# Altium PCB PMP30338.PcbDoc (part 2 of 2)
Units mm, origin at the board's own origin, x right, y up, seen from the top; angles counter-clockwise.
Board outline 50.04 x 70.1 mm, 4 copper layers (Top Layer, GND, Signal Layer, Bottom Layer), stack 2.028 mm thick; 61 components, 55 nets, 302 pads, 122 vias.
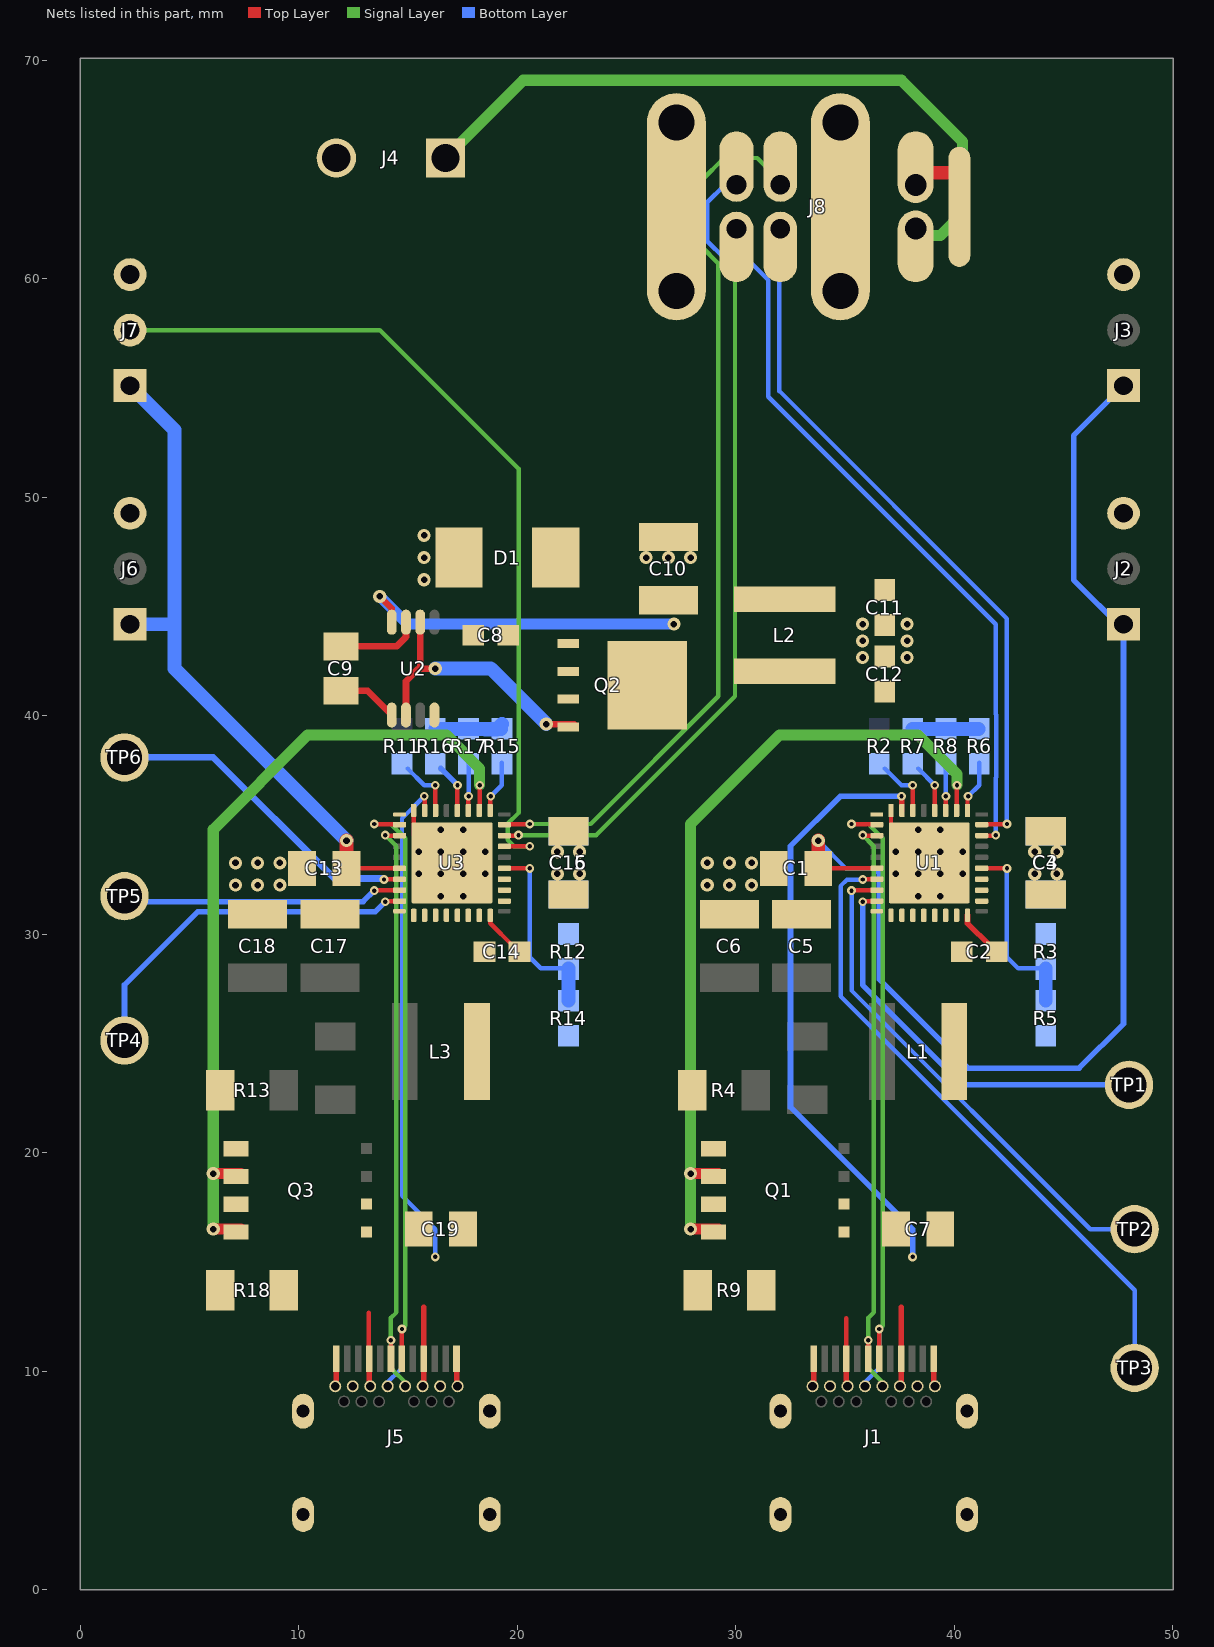
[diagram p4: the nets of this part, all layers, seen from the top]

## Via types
v1: diameter 0.6, hole 0.3, Top Layer to Bottom Layer, 66 vias
v2: diameter 0.4, hole 0.2, Top Layer to Bottom Layer, 52 vias
v3: diameter 5, hole 3, Top Layer to Bottom Layer, 4 vias

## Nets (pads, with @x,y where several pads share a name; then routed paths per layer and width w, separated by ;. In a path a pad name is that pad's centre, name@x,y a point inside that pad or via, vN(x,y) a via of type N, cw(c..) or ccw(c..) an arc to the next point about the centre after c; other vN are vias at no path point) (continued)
CTRL2_2: J7.2 U3.6 | length 39.9
  Top Layer w0.203: U3.6@19.418,34.024 19.418,34.03 v2@20.568,34.03
  Signal Layer w0.203: J7.2@2.286,57.658 13.716,57.658 20.066,51.308 20.066,35.56 19.564,35.058 19.564,34.336 19.858,34.042 20.568,34.042 v2(20.574,34.036)
DN_IN_1: J1.A7 J1.B7 U1.17 | length 29.6
  Top Layer w0.203: v2@35.312,35.046 36.462,35.046 U1.17@36.462,35.024 ; J1.A7@36.572,10.58 v2@36.572,11.934
  Signal Layer w0.203: v2(35.306,35.052) 36.068,35.052 36.725,34.395 36.725,12.087 v2(36.576,11.938)
  Bottom Layer w0.203: J1.B7@35.814,9.398 36.576,10.16 v2(36.576,11.938)
DN_IN_2: J5.A7 J5.B7 U3.17 | length 29.6
  Top Layer w0.203: v2@13.468,35.046 14.618,35.046 U3.17@14.618,35.024 ; J5.A7@14.728,10.58 v2@14.728,11.934
  Signal Layer w0.203: v2(13.462,35.052) 14.224,35.052 14.881,34.395 14.881,31.855 ; v2(14.732,11.938) 14.881,12.087 14.881,31.842
  Bottom Layer w0.203: J5.B7@13.97,9.398 14.732,10.16 v2(14.732,11.938)
DN_OUT_1: J8.1 J8.@32.041,61.463 U1.8 | length 32.4
  Top Layer w0.203: U1.8@41.262,35.024 41.262,35.046 v2@42.412,35.046
  Bottom Layer w0.203: J8.1@32.004,61.976 32.004,54.864 42.418,44.45 v2(42.418,35.052)
DN_OUT_2: J8.2 J8.@32.041,65.137 U3.8 | length 40.6
  Top Layer w0.203: U3.8@19.418,35.024 19.418,35.046 v2@20.568,35.046
  Signal Layer w0.203: v2(20.574,35.052) 23.368,35.052 29.21,40.894 29.21,60.706 28.448,61.468 28.448,64.516 29.464,65.532 30.988,65.532 J8.2@32.004,64.516
DP_IN_1: J1.A6 J1.B6 U1.18 | length 27.3
  Top Layer w0.203: v2@35.834,34.524 U1.18@36.462,34.524 ; J1.A6@36.072,10.58 v2@36.072,11.426
  Signal Layer w0.203: v2(35.814,34.544) 36.322,34.036 36.322,12.7 36.068,12.446 v2(36.068,11.43) 36.068,10.16 J1.B6@36.83,9.398
DP_IN_2: J5.A6 J5.B6 U3.18 | length 27.4
  Top Layer w0.203: v2@13.99,34.524 U3.18@14.618,34.524 ; J5.A6@14.228,10.58 v2@14.228,11.426
  Signal Layer w0.203: v2(13.97,34.544) 14.478,34.036 14.478,32.637 ; 14.478,32.766 14.478,12.7 14.224,12.446 v2(14.224,11.43) 14.224,10.16 J5.B6@14.986,9.398
DP_OUT_1: J8.3 J8.@30.041,65.137 U1.7 | length 36.7
  Top Layer w0.203: U1.7@41.262,34.524 v2@41.89,34.524
  Bottom Layer w0.203: J8.3@29.464,64.262 28.702,63.5 28.702,61.722 29.464,60.96 30.48,60.96 31.496,59.944 31.496,54.61 41.91,44.196 41.91,40.065 41.926,40.049 41.926,37.183 41.91,37.167 v2(41.91,34.544)
DP_OUT_2: J8.4 J8.@30.041,61.463 U3.7 | length 34.2
  Top Layer w0.203: U3.7@19.418,34.524 v2@20.046,34.524
  Signal Layer w0.203: v2(20.066,34.544) 23.622,34.544 29.972,40.894 J8.4@29.972,61.976
GND: C1.2 C3.2 C4.2 C5.2 C6.2 C7.2 C8.2 C10.2 C11.2 C12.2 C13.2 C15.2 C16.2 C17.2 C18.2 C19.2 D1.1 J1.A1 J1.A12 J1.B1 J1.B12 J1.M1 J1.M2 J1.S1 J1.S2 J1.S3 J1.S4 J2.3 J3.3 J4.2 J5.A1 J5.A12 J5.B1 J5.B12 J5.M1 J5.M2 J5.S1 J5.S2 J5.S3 J5.S4 J6.3 J7.3 J8.6 J8.@27.291,59.45 J8.@27.291,67.15 J8.@34.791,59.45 J8.@34.791,67.15 J8.@38.241,65.112 J8.S1 J8.S2 J8.S3 R5.1 R6.1 R7.1 R8.1 R14.1 R15.1 R16.1 R17.1 U1.16 U1.25 U1.26 U1.27 U1.33@38.862,33.274 U1.A3 U1.A4 U3.16 U3.25 U3.26 U3.27 U3.33@17.018,33.274 U3.A3 U3.A4 | length 15.1
  Top Layer w0.203: U3.33@15.268,34.572 U3.16@15.268,35.674 ; U1.33@37.112,34.826 U1.16@37.112,35.674
  Top Layer w0.254: J5.B12@11.728,9.442 J5.A1@11.728,10.58 ; J5.B1@17.228,9.442 J5.A12@17.228,10.58 ; J1.B12@33.572,9.442 J1.A1@33.572,10.58 ; J1.B1@39.072,9.442 J1.A12@39.072,10.58
  Top Layer w0.635: J8.@38.241,64.858 J8.S3@39.966,64.858
  Bottom Layer w0.635: R16.1@16.258,39.408 R17.1@17.782,39.408 R15.1@19.266,39.408 ; 18.542,39.37 19.05,39.37 R15.1@19.304,39.624 ; R7.1@38.102,39.408 R8.1@39.626,39.408 R6.1@41.11,39.408
  other v1: 16.51,31.75 17.526,31.75 38.354,31.75 39.37,31.75 7.112,32.258 8.128,32.258 9.144,32.258 28.702,32.258 29.718,32.258 30.734,32.258 15.494,32.766 16.51,32.766 17.526,32.766 18.542,32.766 37.338,32.766 38.354,32.766 39.37,32.766 40.386,32.766 7.112,33.274 8.128,33.274 9.144,33.274 28.702,33.274 29.718,33.274 30.734,33.274 15.494,33.782 16.51,33.782 17.526,33.782 18.542,33.782 21.844,33.782 22.86,33.782 37.338,33.782 38.354,33.782 39.37,33.782 40.386,33.782 43.688,33.782 44.704,33.782 16.51,34.798 17.526,34.798 38.354,34.798 39.37,34.798 35.814,42.672 37.846,42.672 35.814,43.434 37.846,43.434 35.814,44.196 37.846,44.196 15.748,46.228 15.748,47.244 25.908,47.244 26.924,47.244 27.94,47.244 15.748,48.26
NetC2_1: C2.1 L1.1 U1.28 U1.29 U1.30 U1.31
NetC2_2: C2.2 U1.32 | length 1.8
  Top Layer w0.254: U1.32@40.612,30.874 40.612,30.508 C2.2@41.656,29.464
NetC3_1: C3.1 C4.1 C12.1 C15.1 C16.1 L2.2 R3.2 R12.2 U1.1 U1.2 U1.3 U3.1 U3.2 U3.3
  other v1: 21.844,32.766 22.86,32.766 43.688,32.766 44.704,32.766
NetC9_1: C9.1 U2.7 | length 3.8
  Top Layer w0.305: C9.1@11.938,43.18 14.478,43.18 14.915,43.617 U2.7@14.915,44.289
NetC9_2: C9.2 U2.1 | length 3
  Top Layer w0.305: C9.2@11.684,41.148 13.156,41.148 U2.1@14.265,40.039
NetC10_1: C10.1 C11.1 L2.1 Q2.5 U2.8 | length 15.4
  Top Layer w0.305: v1(13.716,45.466) 14.265,44.917 U2.8@14.265,44.289
  Bottom Layer w0.508: v1(13.716,45.466) 14.986,44.196 v1(27.178,44.196)
NetC14_1: C14.1 L3.1 U3.28 U3.29 U3.30 U3.31
NetC14_2: C14.2 U3.32 | length 1.8
  Top Layer w0.203: U3.32@18.768,30.874 18.768,30.508 C14.2@19.812,29.464
NetQ1_1: Q1.1 Q1.3 R4.1 R9.2
NetQ1_2: Q1.2 Q1.4 U1.10 | length 37.4
  Top Layer w0.203: U1.10@40.112,35.674 40.126,35.688 v2@40.126,36.824
  Top Layer w0.508: v1(27.94,16.51) Q1.4@29.21,16.51 ; v1(27.94,19.05) Q1.2@29.21,19.05
  Signal Layer w0.508: v1(27.94,16.51) v1(27.94,19.05) 27.94,35.052 32.004,39.116 38.354,39.116 40.132,37.338 v2(40.132,36.83)
NetQ2_4: Q2.4 U2.2 U2.6 | length 12.6
  Top Layer w0.305: U2.2@14.915,40.039 14.915,41.585 15.494,42.164 v1(16.256,42.164) ; 15.565,42.235 U2.6@15.565,44.289 ; v1(21.336,39.624) Q2.4@22.606,39.624
  Bottom Layer w0.635: v1(16.256,42.164) 18.796,42.164 v1(21.336,39.624)
NetQ3_1: Q3.1 Q3.3 R13.1 R18.2
NetQ3_2: Q3.2 Q3.4 U3.10 | length 37.4
  Top Layer w0.203: U3.10@18.268,35.674 18.282,35.688 v2@18.282,36.824
  Top Layer w0.508: v1(6.096,16.51) Q3.4@7.366,16.51 ; v1(6.096,19.05) Q3.2@7.366,19.05
  Signal Layer w0.508: v1(6.096,16.51) v1(6.096,19.05) 6.096,34.798 10.414,39.116 16.764,39.116 18.288,37.592 v2(18.288,36.83)
NetR2_1: R2.1 U1.14 | length 2.7
  Top Layer w0.203: v2@38.106,36.824 38.106,35.68 U1.14@38.112,35.674
  Bottom Layer w0.203: R2.1@36.83,37.592 37.592,36.83 v2(38.1,36.83)
NetR3_1: R3.1 R5.2 U1.4 | length 8.7
  Top Layer w0.203: U1.4@41.262,33.024 v2@42.414,33.024
  Bottom Layer w0.203: v2(42.418,33.02) 42.418,28.956 42.926,28.448 R3.1@44.196,28.448
  Bottom Layer w0.635: R5.2@44.196,26.962 R3.1@44.196,28.41 R3.1@44.196,28.448
NetR6_2: R6.2 U1.9 | length 2.4
  Top Layer w0.203: U1.9@40.612,35.674 v2@40.612,36.294
  Bottom Layer w0.203: v2(40.64,36.322) 41.148,36.83 R6.2@41.148,37.846
NetR7_2: R7.2 U1.12 | length 2.2
  Top Layer w0.203: U1.12@39.112,35.674 v2@39.112,36.826
  Bottom Layer w0.203: R7.2@38.354,37.592 v2(39.116,36.83)
NetR8_2: R8.2 U1.11 | length 2.2
  Top Layer w0.203: U1.11@39.612,35.674 v2@39.612,36.31
  Bottom Layer w0.203: v2(39.624,36.322) R8.2@39.624,37.846
NetR11_1: R11.1 U3.14 | length 2.7
  Top Layer w0.203: v2@16.262,36.824 16.262,35.68 U3.14@16.268,35.674
  Bottom Layer w0.203: R11.1@14.986,37.592 15.748,36.83 v2(16.256,36.83)
NetR12_1: R12.1 R14.2 U3.4 | length 8.7
  Top Layer w0.203: U3.4@19.418,33.024 v2@20.57,33.024
  Bottom Layer w0.203: v2(20.574,33.02) 20.574,28.956 21.082,28.448 R12.1@22.352,28.448
  Bottom Layer w0.635: R14.2@22.352,26.962 R12.1@22.352,28.41 R12.1@22.352,28.448
NetR15_2: R15.2 U3.9 | length 2.4
  Top Layer w0.203: U3.9@18.768,35.674 v2@18.768,36.294
  Bottom Layer w0.203: v2(18.796,36.322) 19.304,36.83 R15.2@19.304,37.846
NetR16_2: R16.2 U3.12 | length 2.2
  Top Layer w0.203: U3.12@17.268,35.674 v2@17.268,36.826
  Bottom Layer w0.254: R16.2@16.51,37.592 v2(17.272,36.83)
NetR17_2: R17.2 U3.11 | length 2.2
  Top Layer w0.203: U3.11@17.768,35.674 v2@17.768,36.31
  Bottom Layer w0.203: v2(17.78,36.322) R17.2@17.78,37.846
NetTP1_1: TP1.1 U1.24 | length 18.5
  Top Layer w0.203: v2@35.842,31.524 U1.24@36.462,31.524
  Bottom Layer w0.254: v2(35.814,31.496) 35.814,27.686 40.386,23.114 TP1.1@48.006,23.114
NetTP2_1: TP2.1 U1.23 | length 23.2
  Top Layer w0.203: v2@35.312,32.01 36.462,32.01 U1.23@36.462,32.024
  Bottom Layer w0.203: v2(35.306,32.004) 35.306,27.432 46.228,16.51 TP2.1@48.26,16.51
NetTP3_1: TP3.1 U1.22 | length 29.1
  Top Layer w0.203: v2@35.826,32.524 U1.22@36.462,32.524
  Bottom Layer w0.203: v2(35.814,32.512) 35.808,32.506 35.098,32.506 34.804,32.212 34.804,27.172 48.26,13.716 TP3.1@48.26,10.414
NetTP4_1: TP4.1 U3.24 | length 16.7
  Top Layer w0.203: v2@13.998,31.524 U3.24@14.618,31.524
  Bottom Layer w0.203: TP4.1@2.032,24.892 TP4.1@2.032,25.146
  Bottom Layer w0.254: TP4.1@2.032,25.4 2.032,27.686 5.388,31.042 13.516,31.042 v2(13.97,31.496)
NetTP5_1: TP5.1 U3.23 | length 12.5
  Top Layer w0.203: v2@13.468,32.01 14.618,32.01 U3.23@14.618,32.024
  Bottom Layer w0.254: TP5.1@2.38,31.656 2.54,31.496 12.954,31.496 v2(13.462,32.004)
NetTP6_1: TP6.1 U3.22 | length 14.8
  Top Layer w0.203: v2@13.982,32.524 U3.22@14.618,32.524
  Bottom Layer w0.305: TP6.1@2.032,38.1 6.096,38.1 11.64,32.556 13.867,32.556 v2(13.912,32.512)
VBUS_1: C7.1 J1.A4 J1.A9 J1.B4 J1.B9 Q1.5 Q1.6 R9.1 U1.15 | length 34.3
  Top Layer w0.203: 35.058,12.44 35.058,10.594 J1.A4@35.072,10.58
  Top Layer w0.254: J1.B9@35.072,9.418 J1.A4@35.072,10.58 ; J1.B4@37.572,9.418 J1.A9@37.572,10.58 37.572,12.934 ; U1.15@37.612,35.674 v2@37.612,36.302
  Bottom Layer w0.254: v2(37.592,36.322) 34.798,36.322 32.512,34.036 32.512,22.098 38.1,16.51 v2(38.1,15.24)
VBUS_2: C19.1 J5.A4 J5.A9 J5.B4 J5.B9 Q3.5 Q3.6 R18.1 U3.15 | length 29.6
  Top Layer w0.203: 13.214,12.694 13.214,10.594 J5.A4@13.228,10.58 ; U3.15@15.768,35.674 v2@15.768,36.302
  Top Layer w0.254: J5.B9@13.228,9.418 J5.A4@13.228,10.58 ; J5.B4@15.728,9.418 J5.A9@15.728,10.58 15.728,12.934
  Bottom Layer w0.203: v2(15.748,36.322) 14.732,35.306 14.732,18.034 16.256,16.51 v2(16.256,15.24)
VCC1: C1.1 J2.1 J3.1 U1.21 | length 56.4
  Top Layer w0.203: C1.1@33.786,33.024 U1.21@36.462,33.024
  Top Layer w0.635: C1.1@33.782,33.274 v1(33.782,34.29)
  Bottom Layer w0.203: v1(33.782,34.29) 35.052,33.02 36.322,33.02 36.576,32.766
  Bottom Layer w0.254: 36.576,32.766 36.576,27.94 40.64,23.876 45.72,23.876 47.752,25.908 47.752,43.942 45.466,46.228 45.466,52.832 J3.1@47.498,54.864
VCC2: C13.1 J6.1 J7.1 U3.21 | length 29.9
  Top Layer w0.203: C13.1@12.196,33.024 U3.21@14.618,33.024
  Top Layer w0.635: C13.1@12.192,33.528 v1(12.192,34.29)
  Bottom Layer w0.635: J6.1@2.286,44.196 4.064,44.196 ; J7.1@2.286,55.118 4.318,53.086 4.318,42.164 v1(12.192,34.29)
VIN: C8.1 D1.2 J4.1 J8.5 J8.@38.241,61.488 Q2.1 Q2.2 Q2.3 U2.4 | length 32
  Signal Layer w0.508: J4.1@16.724,65.532 20.28,69.088 37.592,69.088 40.386,66.294 40.386,62.992 39.37,61.976 J8.5@38.354,61.976
pads on no net: J1.A2 J1.A3 J1.A8 J1.A10 J1.A11 J1.B2 J1.B3 J1.B8 J1.B10 J1.B11 J5.A2 J5.A3 J5.A8 J5.A10 J5.A11 J5.B2 J5.B3 J5.B8 J5.B10 J5.B11 U1.33@37.602,32.014 U1.33@37.602,33.274 U1.33@37.602,34.534 U1.33@38.862,32.014 U1.33@38.862,33.274 U1.33@38.862,34.534 U1.33@40.122,32.014 U1.33@40.122,33.274 U1.33@40.122,34.534 U1.A1 U1.A2 U2.3 U2.5 U3.33@15.758,32.014 U3.33@15.758,33.274 U3.33@15.758,34.534 U3.33@17.018,32.014 U3.33@17.018,33.274 U3.33@17.018,34.534 U3.33@18.278,32.014 U3.33@18.278,33.274 U3.33@18.278,34.534 U3.A1 U3.A2
copper on no net:
  other v3: 3.81,3.81 46.228,3.81 3.81,66.294 46.228,66.294

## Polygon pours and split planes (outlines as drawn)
GND on Top Layer "GND_L01_P042" (solid, remove dead copper, pour order 42): 0.508,69.596 49.53,69.596 49.53,0.508 0.508,0.508
NetC14_1 on Top Layer "NETC14_1_L01_P002" (solid, remove dead copper, pour order 2): 17.526,26.924 16.764,27.686 16.764,30.988 18.288,30.988 18.288,30.48 19.304,29.464 19.304,22.098 17.526,22.098
NetC2_1 on Top Layer "NETC2_1_L01_P004" (solid, remove dead copper, pour order 4): 39.37,26.924 38.608,27.686 38.608,30.988 40.132,30.988 40.132,30.48 41.148,29.464 41.148,22.098 39.37,22.098
CS+_1 on Top Layer "CS+_1_L01_P006" (solid, remove dead copper, pour order 6): 37.338,21.59 36.576,21.59 33.782,24.384 26.416,24.384 26.416,29.21 35.052,29.21 37.338,26.924
CS+_2 on Top Layer "CS+_2_L01_P008" (solid, remove dead copper, pour order 8): 15.494,21.59 14.732,21.59 11.938,24.384 4.572,24.384 4.572,29.21 13.208,29.21 15.494,26.924
CS-_2 on Top Layer "CS-_2_L01_P012" (solid, remove dead copper, pour order 12): 8.382,23.876 11.938,23.876 14.478,21.336 14.478,18.542 8.382,18.542
CS-_1 on Top Layer "CS-_1_L01_P014" (solid, remove dead copper, pour order 14): 30.226,23.876 33.782,23.876 36.322,21.336 36.322,18.542 30.226,18.542
NetQ1_1 on Top Layer "NETQ1_1_L01_P016" (solid, remove dead copper, pour order 16): 26.416,23.876 29.718,23.876 29.718,12.192 26.416,12.192
NetQ3_1 on Top Layer "NETQ3_1_L01_P018" (solid, remove dead copper, pour order 18): 4.572,23.876 7.874,23.876 7.874,12.446 4.572,12.446
VBUS_2 on Top Layer "VBUS_2_L01_P020" (solid, remove dead copper, pour order 20): 8.128,18.034 16.51,18.034 16.51,12.446 8.128,12.446
VBUS_1 on Top Layer "VBUS_1_L01_P022" (solid, remove dead copper, pour order 22): 29.972,18.034 38.354,18.034 38.354,12.446 29.972,12.446
NetC10_1 on Top Layer "NETC10_1_L01_P024" (solid, remove dead copper, pour order 24): 23.622,46.482 37.846,46.482 37.846,44.958 35.052,44.958 35.052,44.196 35.052,43.434 28.956,43.434 28.956,38.608 23.622,38.608
GND on Top Layer "GND_L01_P026" (solid, remove dead copper, pour order 26): 35.306,44.704 38.354,44.704 38.354,42.164 35.306,42.164
GND on Top Layer "GND_L01_P032" (solid, remove dead copper, pour order 32): 4.572,34.29 11.176,34.29 11.176,31.75 12.7,31.75 13.208,31.242 16.51,31.242 16.51,27.94 14.732,27.94 12.954,29.718 4.572,29.718
GND on Top Layer "GND_L01_P034" (solid, remove dead copper, pour order 34): 26.416,34.29 33.02,34.29 33.02,31.75 34.544,31.75 35.052,31.242 38.354,31.242 38.354,27.94 36.576,27.94 34.798,29.718 26.416,29.718
VIN on Top Layer "VIN_L01_P038" (solid, remove dead copper, pour order 38): 13.97,69.596 13.97,53.848 19.05,48.768 19.05,42.418 17.526,42.418 16.002,40.894 16.002,39.624 23.114,39.624 23.114,69.596
NetC3_1 on Top Layer "NETC3_1_L01_P040" (solid, remove dead copper, pour order 40): 19.304,33.02 19.304,30.988 25.908,30.988 25.908,34.798 33.782,34.798 33.782,37.592 45.466,37.592 45.466,33.02 41.148,33.02 41.148,30.734 49.53,30.734 49.53,42.926 29.464,42.926 29.464,38.1 23.368,38.1 23.368,33.02
GND on Bottom Layer "GND_L04_P044" (solid, remove dead copper, pour order 44): 0.508,69.596 49.53,69.596 49.53,0.508 0.508,0.508
NetC3_1 on Bottom Layer "NETC3_1_L04_P028" (solid, remove dead copper, pour order 28): 21.082,33.02 23.622,33.02 23.622,29.21 21.082,29.21
NetC3_1 on Bottom Layer "NETC3_1_L04_P030" (solid, remove dead copper, pour order 30): 42.926,33.02 45.466,33.02 45.466,29.21 42.926,29.21
GND on GND "GND_L02_P036" (solid, remove dead copper, pour order 36): 0.508,0.508 49.53,0.508 49.53,69.596 0.508,69.596

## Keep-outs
Keep-Out Layer:
  lines w0.254: 125.73,-0.127 ccw(c125.73,0) 125.857,0 cw(c125.73,0) 125.73,-0.127
  text ".Layer_Name" at 14.656,-21.806 h1.52

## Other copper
Top Layer:
  pour cut-out: 26.416,0.508 26.416,29.464 26.162,29.464 26.162,0.508
  text ".Layer_Name" at 14.656,-21.806 h1.52
GND:
  pour cut-out: 26.416,0.508 26.416,29.464 26.162,29.464 26.162,0.508
Bottom Layer:
  pour cut-out: 27.432,61.468 27.432,64.008 29.21,65.786 30.226,65.786 33.528,62.484 33.528,55.372 43.942,44.958 43.942,35.56 43.688,35.814 40.64,35.814 40.64,43.434 29.972,54.102 29.972,58.928
  pour cut-out: 26.416,0.508 26.416,29.464 26.162,29.464 26.162,0.508
  text ".Layer_Name" at 14.656,-21.806 h1.52

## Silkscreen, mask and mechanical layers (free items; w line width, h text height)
Top Overlay:
  lines w0.254: 5.08,12.192 33.274,12.192 45.72,12.192 45.72,49.784 5.08,49.784 5.08,12.192
  text "GND" at 43.18,59.69 h1.02
  text "GND" at 4.318,59.436 h1.02
  text "CTRL2_2" at 4.318,56.896 h1.02
  text "CTRL2_1" at 38.862,56.388 h1.02
  text "VCC1" at 4.318,54.356 h1.02
  text "VCC1" at 41.91,54.102 h1.02
  text "38 mm x 41 mm" at 19.304,50.546 h1.02
  text "GND" at 5.588,48.26 h1.02
  text "GND" at 42.418,48.26 h1.02
  text "CTRL1_2" at 5.588,45.974 h1.02
  text "CTRL1_1" at 38.862,45.974 h1.02
  text "VCC2" at 5.588,43.688 h1.02
  text "VCC1" at 41.91,43.688 h1.02
  text "PMP30338 Rev B" at 2.032,21.844 h1.02 r270
  text ".Layer_Name" at 14.656,-21.806 h1.52
Bottom Overlay:
  text ".Layer_Name" at 14.656,-21.806 h1.52
Top Paste:
  text ".Layer_Name" at 14.656,-21.806 h1.52
Bottom Paste:
  text ".Layer_Name" at 14.656,-21.806 h1.52
Top Solder:
  text ".Layer_Name" at 14.656,-21.806 h1.52
  text ".Layer_Name" at 14.656,-21.806 h1.52
Bottom Solder:
  drawing of 599 lines, arcs and shapes, not listed
  text ".Layer_Name" at 14.656,-21.806 h1.52
Drill Guide:
  text ".Layer_Name" at 14.656,-21.806 h1.52
M1 Board Outline:
  lines w0.254: 0,0 0,69.85 50.038,69.85 50.038,0 0,0
  text ".Layer_Name" at 14.656,-21.806 h1.52
M2 Board Dimensions:
  rectangle: 3.175,-10.16 12.7,-6.985
  rectangle: 0,-6.985 3.175,-3.81
  lines w0.178: 0,-6.985 25.4,-6.985 ; 3.175,-10.16 3.175,-3.81 ; 6.35,-10.16 6.35,-3.81 ; 12.7,-10.16 12.7,-3.81 ; 19.05,-10.16 19.05,-3.81 ; 0,-10.16 0,-3.81 25.4,-3.81 25.4,-10.16 0,-10.16
  text ".Layer_Name" at 14.656,-21.806 h1.52
M3 3D STEP Top:
  text ".Layer_Name" at 14.656,-21.806 h1.52
M4 3D STEP Bottom:
  text ".Layer_Name" at 14.656,-21.806 h1.52
M5 Assembly Top:
  lines w0.254: -7.417,-23.626 160.223,-23.626 ; -7.417,-18.462 160.274,-18.462 ; -7.417,-13.297 -7.417,-28.791 94.31,-28.791 160.274,-28.791 160.274,-13.297 -7.404,-13.297 -7.404,-28.791 32.614,-28.791 ; 55.194,-28.791 55.194,-13.297 ; 87.376,-18.462 87.376,-13.297 ; 108.712,-18.462 108.712,-13.297 ; 124.511,-28.956 124.511,-23.804
  text "COMPONENTS MARKED 'DNP' SHOULD NOT BE POPULATED." at 29.299,-8.09 h1.52
  text "ASSEMBLY VARIANT:" at 29.286,-11.024 h1.52
  text ".VariantName" at 55.601,-11.024 h1.52
  text "PCB VIEWED FROM TOP SIDE" at -5.804,-16.654 h1.52
  text "BOARD #:" at 57.099,-16.654 h1.52
  text ".PRJ_Number" at 70.955,-16.654 h1.52
  text "REV:" at 92.405,-16.654 h1.52
  text ".PCB_Rev" at 99.809,-16.654 h1.52
  text "SVN REV:" at 113.69,-16.654 h1.52
  text ".VersionControl_RevNumber" at 126.543,-16.654 h1.52
  text "TID #:" at 57.099,-21.819 h1.52
  text ".TID" at 70.955,-21.819 h1.52
  text "PLOT NAME =" at -5.804,-27.034 h1.52
  text ".plot_File_Name" at 14.656,-27.034 h1.52
  text "GENERATED    :" at 57.15,-27.034 h1.52
  text ".Print_Date" at 79.235,-27.034 h1.52
  text ".Print_Time" at 97.752,-27.034 h1.52
  text "TEXAS INSTRUMENTS" at 129.87,-27.034 h1.52
M6 Assembly Bottom:
  lines w0.254: -7.429,-18.474 160.261,-18.474 ; -7.379,-23.639 160.261,-23.639 ; 28.334,-28.969 28.334,-23.817 ; 44.133,-18.474 44.133,-13.31 ; 65.468,-18.474 65.468,-13.31 ; 97.65,-28.804 97.65,-13.31 ; 120.231,-28.804 160.249,-28.804 160.249,-13.31 -7.429,-13.31 -7.429,-28.804 58.534,-28.804 160.261,-28.804 160.261,-13.31
  text "COMPONENTS MARKED 'DNP' SHOULD NOT BE POPULATED." at 154.991,-8.077 h1.52
  text ".VariantName" at 128.473,-11.024 h1.52
  text "ASSEMBLY VARIANT:" at 154.864,-11.024 h1.52
  text ".VersionControl_RevNumber" at 26.302,-16.667 h1.52
  text "SVN REV:" at 39.154,-16.667 h1.52
  text ".PCB_Rev" at 53.035,-16.667 h1.52
  text "REV:" at 60.439,-16.667 h1.52
  text ".PRJ_Number" at 81.89,-16.667 h1.52
  text "BOARD #:" at 95.745,-16.667 h1.52
  text "PCB VIEWED FROM BOTTOM SIDE" at 158.648,-16.667 h1.52
  text ".TID" at 81.89,-21.831 h1.52
  text "TID #:" at 95.745,-21.831 h1.52
  text "TEXAS INSTRUMENTS" at 22.974,-27.047 h1.52
  text ".Print_Time" at 55.093,-27.047 h1.52
  text ".Print_Date" at 73.609,-27.047 h1.52
  text "GENERATED    :" at 95.694,-27.047 h1.52
  text ".plot_File_Name" at 138.189,-27.047 h1.52
  text "PLOT NAME =" at 158.648,-27.047 h1.52
M9 Title Sheet:
  drawing of 57 lines, arcs and shapes, not listed
  text "1" at 18.792,204.127 h1.78
  text "2" at 82.182,204.127 h1.78
  text "3" at 145.411,204.127 h1.78
  text "4" at 209.08,204.127 h1.78
  text "5" at 272.555,204.127 h1.78
  text "6" at 336.182,204.127 h1.78
  text "A" at -10.579,175.095 h1.78
  text "A" at 365.341,175.095 h1.78
  text "B" at 365.341,114.643 h1.78
  text "B" at -10.579,111.341 h1.78
  text "C" at -10.579,54.318 h1.78
  text "C" at 365.341,54.318 h1.78
  text "PROJECT TITLE:" at 288.125,7.048 h1.14
  text ".PRJ_Title" at 289.395,3.662 h1.78
  text "DESIGNED FOR:" at 288.125,-0.597 h1.14
  text ".PRJ_Customer" at 289.395,-4.153 h1.78
  text "D" at -10.579,-5.88 h1.78
  text "D" at 365.341,-5.88 h1.78
  text "FILE NAME:" at 288.125,-8.217 h1.14
  text ".PCB_File_Name_No_Path" at 289.395,-11.265 h1.78
  text "Texas Instruments (TI) and/or its licensors do not warrant the accuracy or completeness of this specification" at 161.9,-15.376 h1.14
  text "ENGINEER:" at 288.125,-15.583 h1.14
  text "LAYOUT BY:" at 326.352,-15.583 h1.14
  text "or any information contained therein. TI and/or its licensors do not warrant that this design will meet" at 160.757,-18.237 h1.14
  text ".PRJ_Engineer" at 289.395,-19.52 h1.78
  text ".PCB_Layout" at 327.635,-19.52 h1.78
  text "the specifications, will be suitable for your application or fit for any particular purpose, or will operate in" at 160.757,-21.099 h1.14
  text ".Layer_Name" at 14.656,-21.806 h1.52
  text "ALTIUM DESIGNER VERSION:" at 326.352,-23.457 h1.14
  text "an implementation. TI and/or its licensors do not warrant that the design is production worthy. You should" at 160.757,-23.961 h1.14
  text "completely validate and test your design implementation to confirm the system functionality for your application." at 161.9,-26.822 h1.14
  text ".print_Scale" at 289.395,-26.843 h1.78
  text ".Application_BuildNumber" at 327.635,-26.843 h1.78
  text "1" at 18.792,-32.093 h1.78
  text "2" at 82.182,-32.093 h1.78
  text "3" at 145.411,-32.093 h1.78
  text "4" at 209.08,-32.093 h1.78
  text "5" at 272.555,-32.093 h1.78
  text "6" at 336.182,-32.093 h1.78
M10 Fab Notes:
  text ".Layer_Name" at 14.656,-21.806 h1.52
M11 Gerber Information:
  lines w0.254: -7.417,-23.626 160.223,-23.626 ; -7.417,-18.462 160.274,-18.462 ; -7.417,-13.297 -7.417,-28.791 94.31,-28.791 160.274,-28.791 160.274,-13.297 -7.404,-13.297 -7.404,-28.791 32.614,-28.791 ; 55.194,-28.791 55.194,-13.297 ; 87.376,-18.462 87.376,-13.297 ; 108.712,-18.462 108.712,-13.297 ; 124.511,-28.956 124.511,-23.804
  text "ALL ARTWORK VIEWED FROM TOP SIDE" at -5.804,-16.654 h1.52
  text "BOARD #:" at 57.099,-16.654 h1.52
  text ".PRJ_Number" at 70.955,-16.654 h1.52
  text "REV:" at 92.405,-16.654 h1.52
  text ".PCB_Rev" at 99.809,-16.654 h1.52
  text "SVN REV:" at 113.69,-16.654 h1.52
  text ".VersionControl_RevNumber" at 126.543,-16.654 h1.52
  text "LAYER NAME =" at -5.804,-21.806 h1.52
  text "TID #:" at 57.099,-21.819 h1.52
  text ".TID" at 70.955,-21.819 h1.52
  text "PLOT NAME =" at -5.804,-27.034 h1.52
  text ".plot_File_Name" at 14.656,-27.034 h1.52
  text "GENERATED    :" at 57.15,-27.034 h1.52
  text ".Print_Date" at 79.235,-27.034 h1.52
  text ".Print_Time" at 97.752,-27.034 h1.52
  text "TEXAS INSTRUMENTS" at 129.87,-27.034 h1.52
M12 Stackup:
  text ".Layer_Name" at 14.656,-21.806 h1.52
M13 Component Bodies Top:
  text ".Layer_Name" at 14.656,-21.806 h1.52
M14 Component Bodies Bottom:
  text ".Layer_Name" at 14.656,-21.806 h1.52
M15 Courtyards Top:
  text ".Layer_Name" at 14.656,-21.806 h1.52
M16 Courtyards Bottom:
  text ".Layer_Name" at 14.656,-21.806 h1.52
Drill Drawing:
  text ".Layer_Name" at 14.656,-21.806 h1.52

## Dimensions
0,-10.16 to 25.4,-10.16 on M2 Board Dimensions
